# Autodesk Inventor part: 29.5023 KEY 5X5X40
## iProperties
Created: 2007-04
Part Number: 29.5023 KEY 5X5X40
Material: Steel
Document SubType Name: Modeling
Designer: Andy Moles
Mass: 7.64035 g
Surface Area: 8.1781 cm^2
Volume: 0.973293 cm^3
Density: 7.85 g/cm^3
Author: Andy Moles
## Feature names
1. Extrusion1
